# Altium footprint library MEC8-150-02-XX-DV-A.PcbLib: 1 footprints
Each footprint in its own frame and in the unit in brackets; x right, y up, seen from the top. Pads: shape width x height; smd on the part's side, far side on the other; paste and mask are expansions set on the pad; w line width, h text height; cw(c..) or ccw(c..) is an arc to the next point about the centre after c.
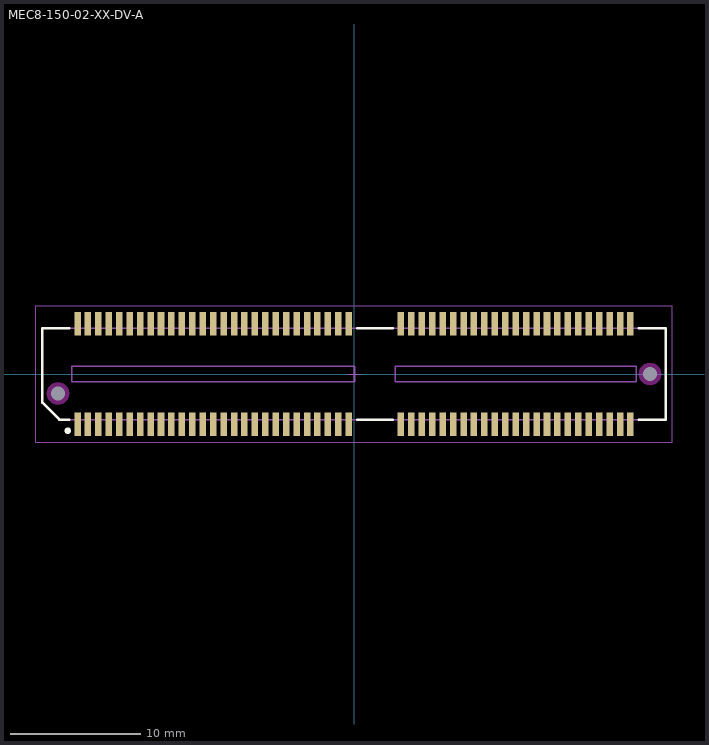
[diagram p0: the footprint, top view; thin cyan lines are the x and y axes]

## MEC8-150-02-XX-DV-A [mm] "0.80mm pitch, mini-edge card assembly; vertical, double row"
height 8.65
pads (102):
  rect 0.5x1.8 smd mask+0: 1(-21.2,-3.85) 2(-21.2,3.85) 3(-20.4,-3.85) 4(-20.4,3.85) 5(-19.6,-3.85) 6(-19.6,3.85) 7(-18.8,-3.85) 8(-18.8,3.85) 9(-18,-3.85) 10(-18,3.85) 11(-17.2,-3.85) 12(-17.2,3.85) 13(-16.4,-3.85) 14(-16.4,3.85) 15(-15.6,-3.85) 16(-15.6,3.85) 17(-14.8,-3.85) 18(-14.8,3.85) 19(-14,-3.85) 20(-14,3.85) 21(-13.2,-3.85) 22(-13.2,3.85) 23(-12.4,-3.85) 24(-12.4,3.85) 25(-11.6,-3.85) 26(-11.6,3.85) 27(-10.8,-3.85) 28(-10.8,3.85) 29(-10,-3.85) 30(-10,3.85) 31(-9.2,-3.85) 32(-9.2,3.85) 33(-8.4,-3.85) 34(-8.4,3.85) 35(-7.6,-3.85) 36(-7.6,3.85) 37(-6.8,-3.85) 38(-6.8,3.85) 39(-6,-3.85) 40(-6,3.85) 41(-5.2,-3.85) 42(-5.2,3.85) 43(-4.4,-3.85) 44(-4.4,3.85) 45(-3.6,-3.85) 46(-3.6,3.85) 47(-2.8,-3.85) 48(-2.8,3.85) 49(-2,-3.85) 50(-2,3.85) 51(-1.2,-3.85) 52(-1.2,3.85) 53(-0.4,-3.85) 54(-0.4,3.85) 55(3.6,-3.85) 56(3.6,3.85) 57(4.4,-3.85) 58(4.4,3.85) 59(5.2,-3.85) 60(5.2,3.85) 61(6,-3.85) 62(6,3.85) 63(6.8,-3.85) 64(6.8,3.85) 65(7.6,-3.85) 66(7.6,3.85) 67(8.4,-3.85) 68(8.4,3.85) 69(9.2,-3.85) 70(9.2,3.85) 71(10,-3.85) 72(10,3.85) 73(10.8,-3.85) 74(10.8,3.85) 75(11.6,-3.85) 76(11.6,3.85) 77(12.4,-3.85) 78(12.4,3.85) 79(13.2,-3.85) 80(13.2,3.85) 81(14,-3.85) 82(14,3.85) 83(14.8,-3.85) 84(14.8,3.85) 85(15.6,-3.85) 86(15.6,3.85) 87(16.4,-3.85) 88(16.4,3.85) 89(17.2,-3.85) 90(17.2,3.85) 91(18,-3.85) 92(18,3.85) 93(18.8,-3.85) 94(18.8,3.85) 95(19.6,-3.85) 96(19.6,3.85) 97(20.4,-3.85) 98(20.4,3.85) 99(21.2,-3.85) 100(21.2,3.85)
  round 0.5 hole 1.05 unplated mask+0: 101(-22.7,-1.5) 102(22.7,0)
Top Overlay:
  circle w0.25: c-21.95,-4.35 r0.125
  lines w0.2: -21.85,-3.5 -22.6,-3.5 -23.9,-2.2 -23.9,3.5 -21.85,3.5 ; 0.25,-3.5 2.95,-3.5 ; 0.25,3.5 2.95,3.5 ; 21.85,-3.5 23.9,-3.5 23.9,3.5 21.85,3.5
Keep-Out Layer:
  pour cut-out: -21.843,-1.5 -21.872,-1.278 -21.958,-1.071 -22.094,-0.894 -22.271,-0.758 -22.478,-0.672 -22.7,-0.643 -22.922,-0.672 -23.129,-0.758 -23.306,-0.894 -23.442,-1.071 -23.528,-1.278 -23.557,-1.5 -23.528,-1.722 -23.442,-1.929 -23.306,-2.106 -23.129,-2.242 -22.922,-2.328 -22.7,-2.357 -22.478,-2.328 -22.271,-2.242 -22.094,-2.106 -21.958,-1.929 -21.872,-1.722
  pour cut-out: 23.557,0 23.528,0.222 23.442,0.429 23.306,0.606 23.129,0.742 22.922,0.828 22.7,0.857 22.478,0.828 22.271,0.742 22.094,0.606 21.958,0.429 21.872,0.222 21.843,0 21.872,-0.222 21.958,-0.429 22.094,-0.606 22.271,-0.742 22.478,-0.828 22.7,-0.857 22.922,-0.828 23.129,-0.742 23.306,-0.606 23.442,-0.429 23.528,-0.222
Mechanical 12:
  lines w0.001: -23.9,-2.2 -22.6,-3.5 23.9,-3.5 23.9,3.5 -23.9,3.5 -23.9,-2.2
Mechanical 13:
  lines w0.1: -23.9,-2.2 -22.6,-3.5 23.9,-3.5 23.9,3.5 -23.9,3.5 -23.9,-2.2 ; -21.65,-0.6 0.05,-0.6 0.05,0.6 -21.65,0.6 -21.65,-0.6 ; 3.15,-0.6 21.65,-0.6 21.65,0.6 3.15,0.6 3.15,-0.6
  text ".Designator" at 0.254,0.254 h1.52
Mechanical 15:
  lines w0.05: -0.5,0 0.5,0 ; 0,-0.5 0,0.5 ; -24.4,-5.25 24.4,-5.25 24.4,5.25 -24.4,5.25 -24.4,-5.25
